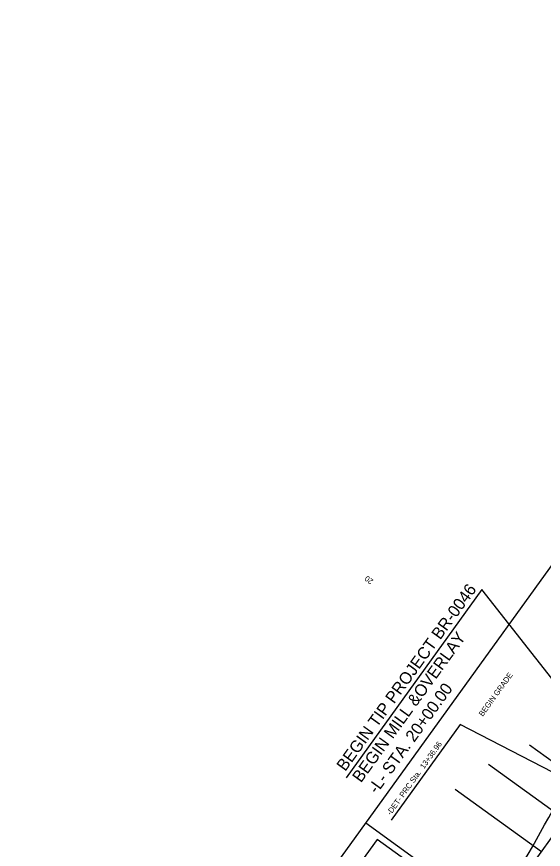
# Model space of a CAD drawing. Extents: x 2189281 to 2191267, y 386656 to 389012.
# Drawn here: x 2189367 to 2190029, y 387465 to 388512 of the extents above; entities that cross this region are included whole.
import ezdxf

# ---------------------------------------------------------------- set-up
doc = ezdxf.new("R2010")
doc.units = 0
for name, color, linetype in [('Prop DSN Text', 7, 'Continuous'), ('Prop Horizontal Alignment', 7, 'Continuous'), ('Prop Horizontal Alignment Station Label', 7, 'Continuous'), ('Prop Horizontal Alignment Tick Label', 7, 'Continuous'), ('Scratch_Level_3', 7, 'Continuous'), ('Scratch_Level_5', 7, 'Continuous')]:
    doc.layers.add(name, color=color, linetype=linetype)

msp = doc.modelspace()

# ---------------------------------------------------------------- linework, layer by layer
at = {"layer": 'Prop DSN Text'}
for p, q in [((2189951.8, 387791.9), (2189781, 387555.2)), ((2190114.3, 387584.2), (2189951.8, 387791.9))]:
    msp.add_line(p, q, dxfattribs=at)
at = {"layer": 'Prop Horizontal Alignment'}
msp.add_line((2189529.4, 386773.1), (2190699.2, 388395.3), dxfattribs=at)
msp.add_arc((2188018.5, 388610.2), 2300, 324.2018, 332.5959, dxfattribs=at)
at = {"layer": 'Prop Horizontal Alignment Station Label'}
for p, q in [((2189924.4, 387622.1), (2189837.6, 387501.8)), ((2190059.1, 387552.3), (2189924.4, 387622.1))]:
    msp.add_line(p, q, dxfattribs=at)
at = {"layer": 'Scratch_Level_3'}
msp.add_lwpolyline([(2189820.2, 387477.5), (2189563.1, 387121.1), (2189763.8, 386976.3), (2190020.9, 387332.7)], close=True, dxfattribs=at)
at = {"layer": 'Scratch_Level_5'}
for p, q in [((2189367.2, 386890.1), (2190537, 388512.3)), ((2190011.6, 387596.6), (2190085.1, 387543.6)), ((2189960.1, 387572.1), (2190055.8, 387503.1)), ((2189917.9, 387540.9), (2190026.6, 387462.5)), ((2189805.9, 387498.4), (2190093.9, 387290.6))]:
    msp.add_line(p, q, dxfattribs=at)

# ---------------------------------------------------------------- texts
at = {"layer": 'Prop DSN Text'}
for s, height, rotation, p in [('BEGIN TIP PROJECT BR-0046', 15, 54.2018, (2189780, 387562.4)), ('BEGIN MILL &OVERLAY', 15, 54.2018, (2189799.8, 387548.1)), ('BEGIN GRADE', 7, 54.0597, (2189952.8, 387631.7)), ('-L- STA. 20+00.00', 15, 54.2018, (2189819.6, 387533.9))]:
    msp.add_text(s, height=height, rotation=rotation, dxfattribs=at).set_placement(p)
at = {"layer": 'Prop Horizontal Alignment Station Label'}
msp.add_text('-DET- PRC Sta.  13+36.96', height=7, rotation=54.2018, dxfattribs=at).set_placement((2189837, 387507.5))
at = {"layer": 'Prop Horizontal Alignment Tick Label'}
msp.add_text('20', height=7, rotation=144.2018, dxfattribs=at).set_placement((2189816, 387803.6))

doc.saveas('drawing.dxf')
